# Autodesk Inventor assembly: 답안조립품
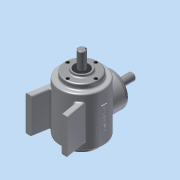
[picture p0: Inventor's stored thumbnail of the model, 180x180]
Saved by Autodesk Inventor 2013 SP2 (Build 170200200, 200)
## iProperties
Created: 2015-01
Part Number: 답안조립품
Document SubType Name: Assembly
Designer: dgall
Author: dgall
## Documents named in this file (15)
- C:\Documents and Settings\dgall\바탕 화면\450105V1027\답안조립품.iam
- C:\Documents and Settings\dgall\바탕 화면\450105V1027\본체.ipt
- C:\Documents and Settings\dgall\바탕 화면\450105V1027\커버.ipt
- C:\Documents and Settings\dgall\바탕 화면\450105V1027\커버2.ipt
- C:\Documents and Settings\dgall\바탕 화면\450105V1027\M4.ipt
- C:\Documents and Settings\dgall\바탕 화면\450105V1027\서브 축.ipt
- 서브 축.ipt
- C:\Documents and Settings\dgall\바탕 화면\450105V1027\메인 축.ipt
- 메인 축.ipt
- C:\Documents and Settings\dgall\바탕 화면\450105V1027\오일실.ipt
- C:\Documents and Settings\dgall\바탕 화면\450105V1027\키 5x5.ipt
- C:\Documents and Settings\dgall\바탕 화면\450105V1027\키 4x4.ipt
- C:\Documents and Settings\dgall\바탕 화면\450105V1027\메인 베벨기어.ipt
- C:\Documents and Settings\dgall\바탕 화면\450105V1027\서브 베벨기어.ipt
- C:\Documents and Settings\dgall\바탕 화면\450105V1027\베어링 6203.ipt
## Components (12 placed, 1 different names)
1. M4:1
2. M4:6
3. M4:7
4. M4:8
5. M4:9
6. M4:10
7. M4:11
8. M4:12
9. M4:2
10. M4:13
11. M4:14
12. M4:15
